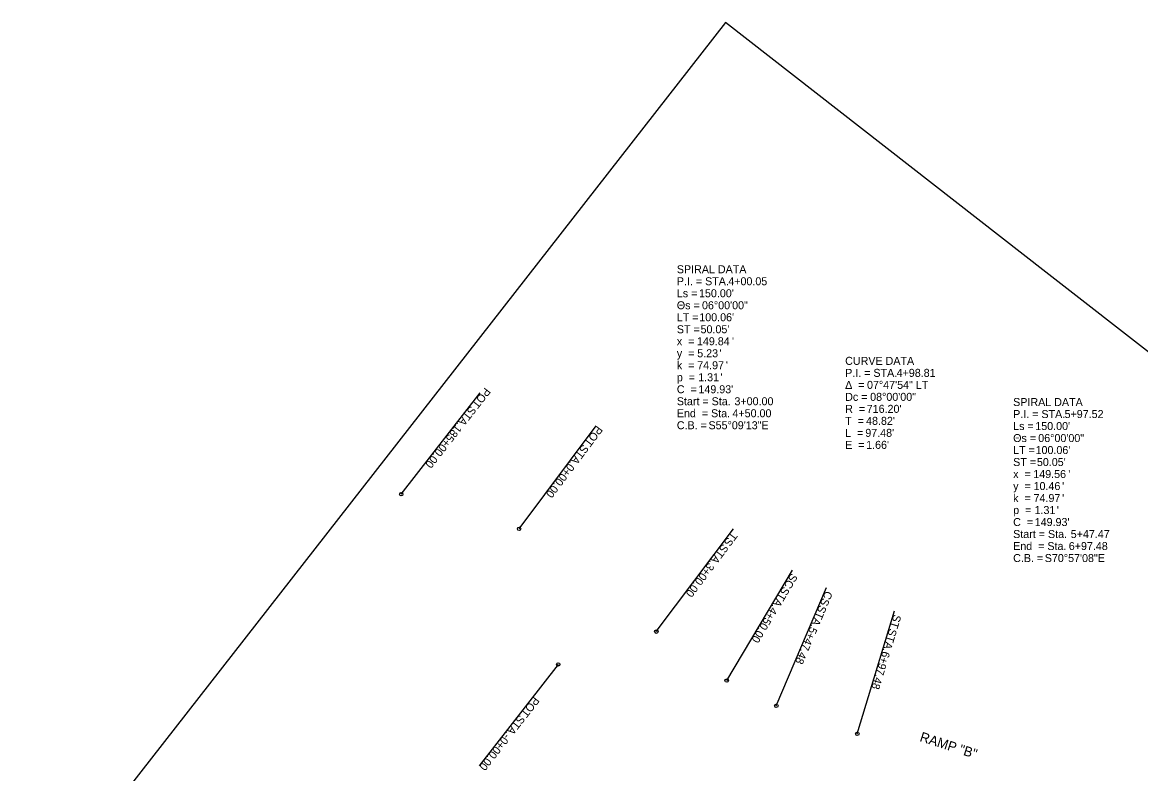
# Model space of a CAD drawing. Extents: x 1323342 to 1326901, y 458396 to 461756.
# Drawn here: x 1323342 to 1325299, y 460441 to 461756 of the extents above; entities that cross this region are included whole.
import ezdxf

# ---------------------------------------------------------------- set-up
doc = ezdxf.new("R2010")
doc.units = 0
for name, color, linetype in [('GE_X_Alignment_500_Cardinal_Points', 7, 'Continuous'), ('GE_X_Alignment_500_Curve_Data', 7, 'Continuous'), ('RD_X_Text', 7, 'Continuous'), ('SH_Named_Boundary', 7, 'Continuous')]:
    doc.layers.add(name, color=color, linetype=linetype)

msp = doc.modelspace()

# ---------------------------------------------------------------- linework, layer by layer
at = {"layer": 'GE_X_Alignment_500_Cardinal_Points'}
for p, q in [((1324005, 460930.6), (1324143.3, 461108)), ((1324211.2, 460869.9), (1324346.2, 461050)), ((1324451.3, 460690), (1324586.2, 460870.1)), ((1324574.4, 460604.3), (1324689.7, 460797.5)), ((1324661.2, 460560.2), (1324749.3, 460767.2)), ((1324802.9, 460511.2), (1324868.2, 460726.6)), ((1324279.7, 460632.6), (1324141.4, 460455.2))]:
    msp.add_line(p, q, dxfattribs=at)
for centre in [(1324005, 460930.6), (1324211.2, 460869.9), (1324451.3, 460690), (1324279.7, 460632.6), (1324574.4, 460604.3), (1324661.2, 460560.2), (1324802.9, 460511.2)]:
    msp.add_circle(centre, 3, dxfattribs=at)
at = {"layer": 'SH_Named_Boundary'}
msp.add_lwpolyline([(1324572.3, 461756.3), (1323342.2, 460179.3), (1323902.4, 459742.4), (1324099.5, 459588.6), (1324299.3, 459432.8), (1324514.7, 459269.4), (1324733.4, 459110.5), (1324955.2, 458956), (1325179.8, 458806.3), (1325389.2, 458669.7), (1325598.5, 458533.1), (1325807.9, 458396.4), (1326900.9, 460071.4), (1326691.5, 460208), (1326482.2, 460344.6), (1326272.8, 460481.2), (1326081.3, 460608.8), (1325892.9, 460740.1), (1325707.1, 460875.1), (1325524.2, 461013.9), (1325329.6, 461165.5), (1325132.5, 461319.3)], close=True, dxfattribs=at)

# ---------------------------------------------------------------- texts
at = {"layer": 'GE_X_Alignment_500_Cardinal_Points'}
for s, rotation, p in [('POT', 232.0433, (1324151.5, 461118.2)), (' STA. ', 232.0433, (1324129.6, 461090.1)), ('185+00.00', 232.0433, (1324100.9, 461053.3)), ('POT', 233.1538, (1324347.4, 461051.3)), (' STA. ', 233.1538, (1324326, 461022.8)), ('0+00.00', 233.1538, (1324298.1, 460985.5)), ('TS', 233.1538, (1324583, 460865.4)), (' STA. ', 233.1538, (1324570.6, 460848.9)), ('3+00.00', 233.1538, (1324542.7, 460811.6)), ('SC', 239.1538, (1324687.3, 460793)), (' STA. ', 239.1538, (1324676.1, 460774.3)), ('CS', 246.9519, (1324747.4, 460762.4)), ('4+50.00', 239.1538, (1324652.2, 460734.3)), (' STA. ', 246.9519, (1324738.9, 460742.3)), ('ST', 253.1349, (1324866.7, 460721)), ('5+47.48', 246.9519, (1324720.6, 460699.5)), (' STA. ', 253.1349, (1324860.7, 460701.3)), ('6+97.48', 253.1349, (1324847.2, 460656.7)), ('POT', 232.0433, (1324237, 460577.4)), (' STA. ', 232.0433, (1324215, 460549.3)), ('-0+00.00', 232.0433, (1324186.4, 460512.6))]:
    msp.add_text(s, height=14, rotation=rotation, dxfattribs=at).set_placement(p)
at = {"layer": 'GE_X_Alignment_500_Curve_Data'}
for s, p in [('SPIRAL DATA', (1324487.2, 461317.2)), ('P.I. = STA. ', (1324487.2, 461296.2)), ('4+00.05', (1324577.2, 461296.2)), ('Ls = ', (1324487.2, 461275.2)), ("150.00'", (1324526, 461275.2)), ('Θs = ', (1324487.2, 461254.2)), ('06°00\'00"', (1324531.2, 461254.2)), ('LT = ', (1324487.2, 461233.2)), ("100.06'", (1324526.5, 461233.2)), ('ST = ', (1324487.2, 461212.2)), ("50.05'", (1324528.7, 461212.2)), ('x  = ', (1324487.2, 461191.2)), ('149.84', (1324522.4, 461191.2)), ("'", (1324583.7, 461191.2)), ('5.23', (1324522.9, 461170.2)), ("'", (1324561.8, 461170.2)), ('y  = ', (1324487.2, 461170.2)), ('k  = ', (1324487.2, 461149.2)), ('74.97', (1324522.9, 461149.2)), ("'", (1324573, 461149.2)), ('CURVE DATA', (1324781.7, 461156.9)), ('P.I. = STA. ', (1324781.7, 461135.9)), ('4+98.81', (1324871.7, 461135.9)), ('p  = ', (1324487.2, 461128.2)), ('1.31', (1324524.6, 461128.2)), ("'", (1324563.5, 461128.2)), ('Δ  = ', (1324781.7, 461114.9)), ('07°47\'54" LT', (1324819.9, 461114.9)), ('C  = ', (1324487.2, 461107.2)), ("149.93'", (1324525, 461107.2)), ('Dc = ', (1324781.7, 461093.9)), ('08°00\'00"', (1324825.4, 461093.9)), ('Start = Sta. ', (1324487.2, 461086.2)), ('3+00.00', (1324588, 461086.2)), ('R  = ', (1324781.7, 461072.9)), ("716.20'", (1324819.4, 461072.9)), ('SPIRAL DATA', (1325075.6, 461084.8)), ('End  = Sta. ', (1324487.2, 461065.2)), ('4+50.00', (1324584.5, 461065.2)), ('T  = ', (1324781.7, 461051.9)), ("48.82'", (1324818.3, 461051.9)), ('P.I. = STA. ', (1325075.6, 461063.8)), ('5+97.52', (1325165.5, 461063.8)), ('C.B. = ', (1324487.2, 461044.2)), ('S55°09\'13"E', (1324542.6, 461044.2)), ('L  = ', (1324781.7, 461030.9)), ("97.48'", (1324816.9, 461030.9)), ('Ls = ', (1325075.6, 461042.8)), ("150.00'", (1325114.3, 461042.8)), ('Θs = ', (1325075.6, 461021.8)), ('06°00\'00"', (1325119.5, 461021.8)), ('E  = ', (1324781.7, 461009.9)), ("1.66'", (1324818.4, 461009.9)), ('LT = ', (1325075.6, 461000.8)), ("100.06'", (1325114.8, 461000.8)), ('ST = ', (1325075.6, 460979.8)), ("50.05'", (1325117.1, 460979.8)), ('x  = ', (1325075.6, 460958.8)), ('149.56', (1325110.8, 460958.8)), ("'", (1325172, 460958.8)), ('y  = ', (1325075.6, 460937.8)), ('10.46', (1325111.3, 460937.8)), ("'", (1325161.3, 460937.8)), ('k  = ', (1325075.6, 460916.8)), ('74.97', (1325111.3, 460916.8)), ("'", (1325161.3, 460916.8)), ('1.31', (1325113, 460895.8)), ("'", (1325151.9, 460895.8)), ('C  = ', (1325075.6, 460874.8)), ('p  = ', (1325075.6, 460895.8)), ("149.93'", (1325113.3, 460874.8)), ('Start = Sta. ', (1325075.6, 460853.8)), ('5+47.47', (1325176.3, 460853.8)), ('End  = Sta. ', (1325075.6, 460832.8)), ('6+97.48', (1325172.9, 460832.8)), ('C.B. = ', (1325075.6, 460811.8)), ('S70°57\'08"E', (1325130.9, 460811.8))]:
    msp.add_text(s, height=14, dxfattribs=at).set_placement(p)
at = {"layer": 'RD_X_Text'}
msp.add_text('RAMP "B"', height=17, rotation=342.2913, dxfattribs=at).set_placement((1324911, 460498.7))

doc.saveas('drawing.dxf')
